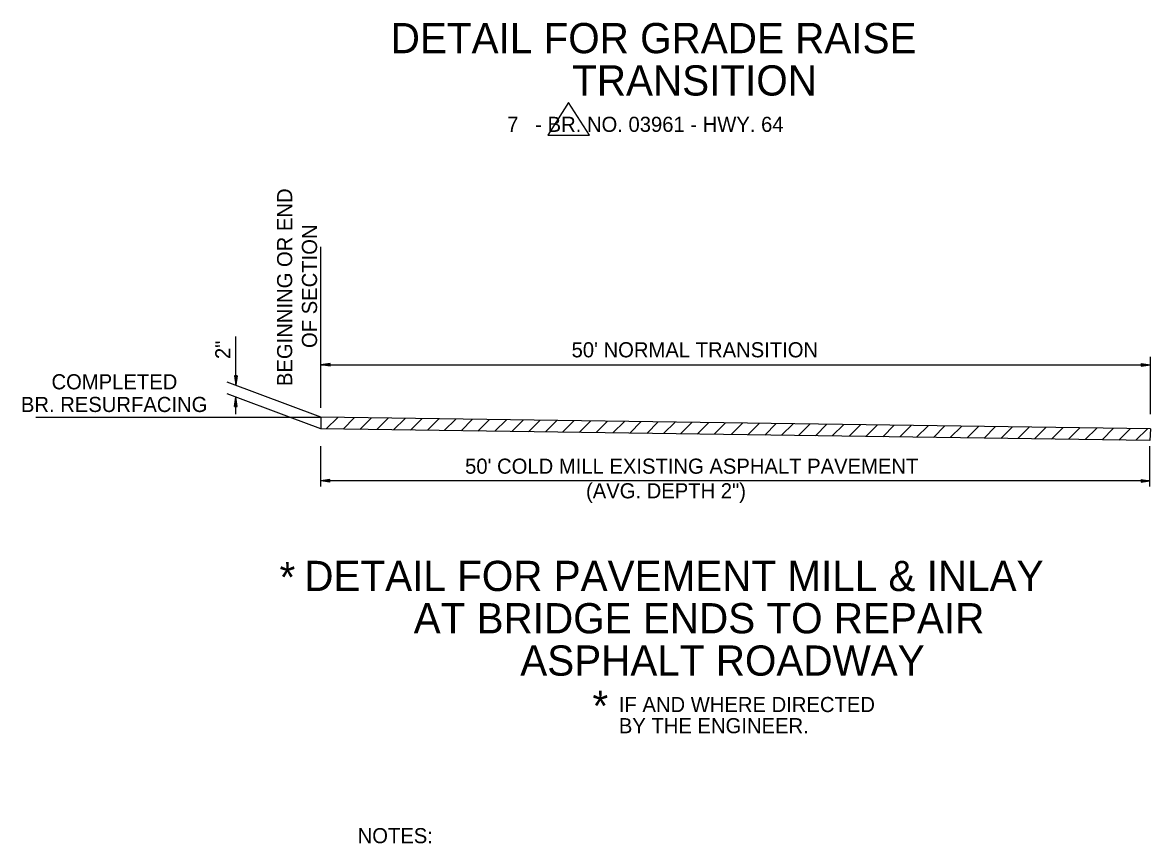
# Model space of a CAD drawing. Extents: x 1926836 to 1933254, y 596317 to 604524.
# Drawn here: x 1928806.1 to 1929253.7, y 600105.1 to 600430.9 of the extents above; entities that cross this region are included whole.
import ezdxf

# ---------------------------------------------------------------- set-up
doc = ezdxf.new("R2010")
doc.units = 0
for name, color, linetype in [('Default', 7, 'Continuous'), ('R_Annotation', 7, 'Continuous'), ('R_Draft', 7, 'Continuous')]:
    doc.layers.add(name, color=color, linetype=linetype)

msp = doc.modelspace()

# ---------------------------------------------------------------- linework, layer by layer
at = {"layer": 'Default'}
for p, q in [((1928924.46, 600278.01), (1928924.46, 600341.91)), ((1928890.71, 600287.09), (1928890.71, 600306.28)), ((1928928.2, 600295.61), (1928924.46, 600295.08)), ((1928924.46, 600295.08), (1929253.71, 600295.08)), ((1928928.2, 600294.55), (1928924.46, 600295.08)), ((1928928.2, 600295.44), (1928925.01, 600295.08)), ((1928928.2, 600294.55), (1928925.01, 600295.08)), ((1928928.2, 600295.44), (1928925.71, 600295.08)), ((1928928.2, 600294.73), (1928925.71, 600295.08)), ((1928928.2, 600295.26), (1928926.43, 600295.08)), ((1928928.2, 600294.73), (1928926.43, 600295.08)), ((1928928.2, 600295.26), (1928926.96, 600295.08)), ((1928928.2, 600294.91), (1928926.96, 600295.08)), ((1928928.2, 600295.08), (1928927.67, 600295.08)), ((1928928.2, 600294.91), (1928927.67, 600295.08)), ((1928928.2, 600294.55), (1928928.2, 600295.61)), ((1929249.97, 600295.61), (1929253.71, 600295.08)), ((1929249.97, 600295.61), (1929249.97, 600294.55)), ((1929249.97, 600295.44), (1929252.47, 600295.08)), ((1929249.97, 600295.44), (1929252.99, 600295.08)), ((1929249.97, 600295.26), (1929251.21, 600295.08)), ((1929249.97, 600295.26), (1929251.76, 600295.08)), ((1929249.97, 600294.55), (1929253.71, 600295.08)), ((1929249.97, 600294.91), (1929251.21, 600295.08)), ((1929249.97, 600294.73), (1929252.47, 600295.08)), ((1929249.97, 600294.55), (1929252.99, 600295.08)), ((1929249.97, 600294.73), (1929251.76, 600295.08)), ((1929249.97, 600294.91), (1929250.51, 600295.08)), ((1929249.97, 600295.08), (1929250.51, 600295.08)), ((1929253.71, 600275.54), (1929253.71, 600298.27)), ((1928890.17, 600290.65), (1928890.71, 600287.09)), ((1928890.17, 600290.65), (1928890.71, 600287.62)), ((1928891.24, 600290.65), (1928890.17, 600290.65)), ((1928890.36, 600290.65), (1928890.71, 600288.34)), ((1928890.36, 600290.65), (1928890.71, 600288.86)), ((1928890.53, 600290.65), (1928890.71, 600289.58)), ((1928890.53, 600290.65), (1928890.71, 600290.1)), ((1928891.24, 600290.65), (1928890.71, 600287.09)), ((1928890.88, 600290.65), (1928890.71, 600289.58)), ((1928891.07, 600290.65), (1928890.71, 600288.34)), ((1928891.07, 600290.65), (1928890.71, 600287.62)), ((1928890.88, 600290.65), (1928890.71, 600288.86)), ((1928890.71, 600290.65), (1928890.71, 600290.1)), ((1928924.46, 600274.29), (1928887.33, 600288.15)), ((1928912.03, 600274.32), (1928887.33, 600283.53)), ((1928890.17, 600278.55), (1928890.71, 600282.28)), ((1928890.17, 600278.55), (1928890.71, 600281.75)), ((1928890.36, 600278.55), (1928890.71, 600281.05)), ((1928891.24, 600278.55), (1928890.71, 600282.28)), ((1928890.71, 600275.54), (1928890.71, 600282.28)), ((1928891.07, 600278.55), (1928890.71, 600281.75)), ((1928891.07, 600278.55), (1928890.71, 600281.05)), ((1928890.17, 600278.55), (1928891.24, 600278.55)), ((1928890.36, 600278.55), (1928890.71, 600280.52)), ((1928890.53, 600278.55), (1928890.71, 600279.8)), ((1928890.53, 600278.55), (1928890.71, 600279.08)), ((1928890.88, 600278.55), (1928890.71, 600280.52)), ((1928890.88, 600278.55), (1928890.71, 600279.8)), ((1928890.71, 600278.55), (1928890.71, 600279.08)), ((1928811.39, 600274.29), (1928924.46, 600274.29)), ((1928924.46, 600269.68), (1928912.03, 600274.32)), ((1929253.71, 600269.68), (1928924.46, 600274.29)), ((1928926.61, 600269.65), (1928931.16, 600274.2)), ((1928933.3, 600269.55), (1928937.85, 600274.1)), ((1928939.99, 600269.46), (1928944.55, 600274.01)), ((1928946.69, 600269.36), (1928951.24, 600273.92)), ((1928953.38, 600269.27), (1928957.93, 600273.82)), ((1928960.08, 600269.18), (1928964.63, 600273.73)), ((1928966.77, 600269.08), (1928971.32, 600273.63)), ((1928973.47, 600268.99), (1928978.02, 600273.54)), ((1928980.16, 600268.89), (1928984.71, 600273.45)), ((1928986.85, 600268.8), (1928991.41, 600273.35)), ((1928993.55, 600268.71), (1928998.1, 600273.26)), ((1929000.24, 600268.61), (1929004.79, 600273.16)), ((1929006.94, 600268.52), (1929011.49, 600273.07)), ((1929013.63, 600268.42), (1929018.18, 600272.98)), ((1929020.32, 600268.33), (1929024.88, 600272.88)), ((1929027.02, 600268.23), (1929031.57, 600272.79)), ((1929033.71, 600268.14), (1929038.27, 600272.7)), ((1929040.41, 600268.05), (1929044.96, 600272.6)), ((1929047.1, 600267.95), (1929051.66, 600272.51)), ((1929053.79, 600267.86), (1929058.35, 600272.41)), ((1929060.49, 600267.76), (1929065.04, 600272.32)), ((1929067.18, 600267.67), (1929071.74, 600272.23)), ((1929073.88, 600267.58), (1929078.43, 600272.13)), ((1929080.57, 600267.48), (1929085.13, 600272.04)), ((1929253.53, 600265.05), (1928924.46, 600269.68)), ((1929087.26, 600267.39), (1929091.82, 600271.95)), ((1929093.96, 600267.29), (1929098.52, 600271.85)), ((1929100.65, 600267.2), (1929105.21, 600271.76)), ((1929107.35, 600267.1), (1929111.91, 600271.66)), ((1929114.04, 600267.01), (1929118.6, 600271.57)), ((1929120.73, 600266.92), (1929125.29, 600271.48)), ((1929127.43, 600266.82), (1929131.99, 600271.38)), ((1929134.12, 600266.73), (1929138.68, 600271.29)), ((1929140.82, 600266.63), (1929145.38, 600271.2)), ((1929147.51, 600266.54), (1929152.07, 600271.1)), ((1929154.2, 600266.45), (1929158.77, 600271.01)), ((1929160.9, 600266.35), (1929165.46, 600270.91)), ((1929167.59, 600266.26), (1929172.16, 600270.82)), ((1929174.29, 600266.16), (1929178.85, 600270.73)), ((1929180.98, 600266.07), (1929185.54, 600270.63)), ((1929187.67, 600265.97), (1929192.24, 600270.54)), ((1929194.37, 600265.88), (1929198.93, 600270.44)), ((1929201.06, 600265.79), (1929205.63, 600270.35)), ((1929207.76, 600265.69), (1929212.32, 600270.26)), ((1929214.45, 600265.6), (1929219.02, 600270.16)), ((1929221.14, 600265.5), (1929225.71, 600270.07)), ((1929227.84, 600265.41), (1929232.41, 600269.98)), ((1929234.53, 600265.31), (1929239.1, 600269.88)), ((1929241.23, 600265.22), (1929245.79, 600269.79)), ((1929247.92, 600265.13), (1929252.49, 600269.69)), ((1929253.71, 600269.68), (1929253.53, 600265.05)), ((1928924.46, 600246.75), (1928924.46, 600262.74)), ((1929253.53, 600246.75), (1929253.53, 600262.74)), ((1928928.03, 600249.59), (1928924.46, 600249.07)), ((1928928.03, 600249.59), (1928924.46, 600249.07)), ((1929253.53, 600249.07), (1928924.46, 600249.07)), ((1928928.03, 600248.53), (1928924.46, 600249.07)), ((1928928.03, 600248.53), (1928924.46, 600249.07)), ((1928928.03, 600249.59), (1928925.01, 600249.07)), ((1928928.03, 600249.59), (1928925.01, 600249.07)), ((1928928.03, 600248.71), (1928925.01, 600249.07)), ((1928928.03, 600248.71), (1928925.01, 600249.07)), ((1928928.03, 600249.43), (1928925.71, 600249.07)), ((1928928.03, 600249.43), (1928925.71, 600249.07)), ((1928928.03, 600248.71), (1928925.71, 600249.07)), ((1928928.03, 600248.71), (1928925.71, 600249.07)), ((1928928.03, 600249.43), (1928926.25, 600249.07)), ((1928928.03, 600249.43), (1928926.25, 600249.07)), ((1928928.03, 600248.89), (1928926.25, 600249.07)), ((1928928.03, 600248.89), (1928926.25, 600249.07)), ((1928928.03, 600249.23), (1928926.96, 600249.07)), ((1928928.03, 600249.23), (1928926.96, 600249.07)), ((1928928.03, 600248.89), (1928926.96, 600249.07)), ((1928928.03, 600248.89), (1928926.96, 600249.07)), ((1928928.03, 600249.23), (1928927.49, 600249.07)), ((1928928.03, 600249.23), (1928927.49, 600249.07)), ((1928928.03, 600249.07), (1928927.49, 600249.07)), ((1928928.03, 600249.07), (1928927.49, 600249.07)), ((1928928.03, 600248.53), (1928928.03, 600249.59)), ((1928928.03, 600248.53), (1928928.03, 600249.59)), ((1929249.97, 600249.59), (1929253.53, 600249.07)), ((1929249.97, 600249.59), (1929252.99, 600249.07)), ((1929249.97, 600249.59), (1929249.97, 600248.53)), ((1929249.97, 600249.43), (1929252.28, 600249.07)), ((1929249.97, 600249.43), (1929251.76, 600249.07)), ((1929249.97, 600249.23), (1929251.05, 600249.07)), ((1929249.97, 600249.23), (1929250.51, 600249.07)), ((1929249.97, 600248.53), (1929253.53, 600249.07)), ((1929249.97, 600248.89), (1929251.05, 600249.07)), ((1929249.97, 600248.71), (1929252.28, 600249.07)), ((1929249.97, 600248.71), (1929252.99, 600249.07)), ((1929249.97, 600248.89), (1929251.76, 600249.07)), ((1929249.97, 600249.07), (1929250.51, 600249.07))]:
    msp.add_line(p, q, dxfattribs=at)
at = {"layer": 'R_Annotation'}
for p, q in [((1929022.8, 600399.22), (1929014.52, 600386.24)), ((1929031.08, 600386.24), (1929022.8, 600399.22)), ((1929014.52, 600386.24), (1929031.08, 600386.24)), ((1928924.46, 600274.29), (1928924.46, 600269.68))]:
    msp.add_line(p, q, dxfattribs=at)

# ---------------------------------------------------------------- texts
at = {"layer": 'Default'}
for s, height, rotation, p in [('DETAIL FOR GRADE RAISE', 12, 360, (1928952.22, 600418.76)), ('TRANSITION', 12, 360, (1929024.19, 600401.96)), ('BEGINNING OR END', 6, 90, (1928913.11, 600286.64)), ('OF SECTION', 6, 90, (1928922.97, 600301.75)), ('2"', 6, 90, (1928888.58, 600297.36)), ("50' NORMAL TRANSITION", 6, 360, (1929023.99, 600298.04)), ('COMPLETED', 6, 360, (1928817.59, 600285.34)), ('BR. RESURFACING', 6, 360, (1928805.45, 600276.34)), ("50' COLD MILL EXISTING ASPHALT PAVEMENT", 6, 360, (1928981.73, 600251.84)), ('(AVG. DEPTH 2")', 6, 360, (1929029.71, 600242.07))]:
    msp.add_text(s, height=height, rotation=rotation, dxfattribs=at).set_placement(p)
at = {"layer": 'R_Annotation'}
for s, height, p in [('*', 12, (1928908.09, 600204.78)), ('DETAIL FOR PAVEMENT MILL & INLAY', 12, (1928917.92, 600205.28)), ('AT BRIDGE ENDS TO REPAIR', 12, (1928961.33, 600188.48)), ('ASPHALT ROADWAY', 12, (1929003.62, 600171.68)), ('*', 12, (1929032.27, 600153.69)), ('IF AND WHERE DIRECTED', 6, (1929042.75, 600157.23)), ('BY THE ENGINEER.', 6, (1929042.75, 600148.83)), ('NOTES:', 6, (1928939.08, 600105.17))]:
    msp.add_text(s, height=height, rotation=360, dxfattribs=at).set_placement(p)
at = {"layer": 'R_Draft'}
msp.add_text('      7   - BR. NO. 03961 - HWY. 64', height=6, dxfattribs=at).set_placement((1928985.05, 600387.54))

doc.saveas('drawing.dxf')
